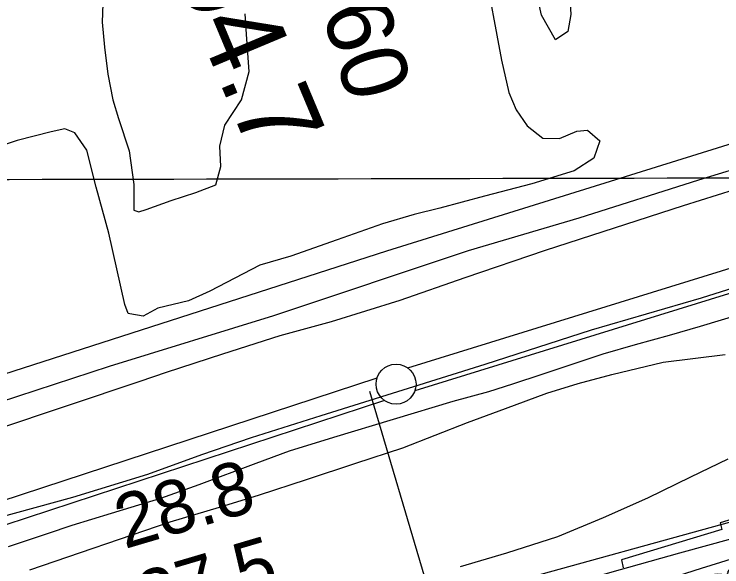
# Model space of a CAD drawing. Extents: x 3324104 to 3361979, y 612876 to 638273.
# Drawn here: x 3357621 to 3358506, y 623884 to 624575 of the extents above; entities that cross this region are included whole.
import ezdxf

# ---------------------------------------------------------------- set-up
doc = ezdxf.new("R2010")
doc.units = 0
for name, color, linetype in [('V-FLOD-BASE', 7, 'Continuous'), ('V-GRID-MAJR', 7, 'Continuous'), ('V-LEVE-TOET', 7, 'Continuous'), ('V-RIVR-EDGE', 7, 'Continuous'), ('V-RIVR-RANG', 7, 'Continuous'), ('V-RIVR-RANG-IDEN', 7, 'Continuous'), ('V-ROAD-CNTR', 7, 'Continuous'), ('V-RRAP-RVMT', 7, 'Continuous'), ('V-SITE-VEGE', 7, 'Continuous'), ('V-SURV-IDEN', 7, 'Continuous'), ('V-SURV-LINE', 7, 'Continuous'), ('V-TOPO-MAJR', 7, 'Continuous'), ('V-TOPO-MINR', 7, 'Continuous'), ('V-TOPO-SHOR', 7, 'Continuous')]:
    doc.layers.add(name, color=color, linetype=linetype)

msp = doc.modelspace()

# ---------------------------------------------------------------- linework, layer by layer
at = {"layer": 'V-FLOD-BASE'}
msp.add_lwpolyline([(3357573.71, 623938.31), (3357694.33, 623971.45), (3357787.75, 624000.32), (3357855.36, 624024.93), (3357917.4, 624046.04), (3358004.54, 624073.49), (3358209.5, 624137.57), (3358342.65, 624180.51), (3358480, 624220.67), (3358576.2, 624250.94), (3358637.54, 624274.14), (3358756.06, 624310.06), (3358978.46, 624376.27), (3359126.95, 624420.65), (3359170.17, 624435.42)], dxfattribs=at)
at = {"layer": 'V-GRID-MAJR'}
msp.add_spline([(3328209.96, 624318.18), (3333474.02, 624325.46), (3338738.09, 624333.49), (3344002.15, 624342.3), (3349266.22, 624351.87), (3354530.28, 624362.21), (3359794.34, 624373.31)], degree=3, dxfattribs=at)
at = {"layer": 'V-LEVE-TOET'}
for points in [[(3359793.54, 624738.78), (3359769.02, 624731.31), (3359688.87, 624701.08), (3359550.81, 624665.1), (3359476.22, 624641.17), (3359417.66, 624623.56), (3359352.12, 624603.84), (3359273.34, 624581.29), (3359195.96, 624556.65), (3359115.09, 624531.31), (3359046.78, 624508.09), (3358864.81, 624455.94), (3358808.34, 624439.04), (3358629.16, 624387.59), (3358542.01, 624362.23), (3358456.96, 624335.48), (3358284.77, 624279.87), (3358184.39, 624245.4), (3358102.84, 624217.26), (3358017.09, 624190.5), (3357952.94, 624172.88), (3357881.14, 624150.34), (3357810.73, 624127.12)], [(3357613.86, 623909.74), (3357662.66, 623925.93), (3357693.33, 623936.48), (3357767.23, 623959.02), (3357804.18, 623970.29), (3357852.28, 623987.17), (3357923.37, 624013.88), (3357965.19, 624029.35), (3358020.27, 624046.25), (3358169.46, 624091.33), (3358214.08, 624103.31), (3358244.06, 624113.17), (3358281.01, 624125.13), (3358356.99, 624150.47), (3358397.43, 624162.44), (3358439.96, 624173.72), (3358479, 624185), (3358527.1, 624199.79)], [(3357810.73, 624127.12), (3357777.97, 624115.86), (3357596.02, 624055.34)]]:
    msp.add_lwpolyline(points, dxfattribs=at)
at = {"layer": 'V-RIVR-EDGE'}
msp.add_spline([(3359795.11, 624016.82), (3359789.29, 624017.27), (3359775.9, 624016.6), (3359757.21, 624013.48), (3359746.28, 624008.22), (3359732.18, 624007.9), (3359730.42, 624010.02), (3359727.96, 624012.14), (3359719.16, 624015.33), (3359708.94, 624015.01), (3359699.42, 624012.92), (3359694.14, 624013.99), (3359689.92, 624019.28), (3359671.6, 624018.62), (3359656.8, 624018.66), (3359645.88, 624019.39), (3359641.64, 624017.99), (3359635.65, 624018.01), (3359628.96, 624018.73), (3359625.43, 624017.68), (3359622.61, 624015.92), (3359617.68, 624018.4), (3359614.16, 624018.06), (3359610.63, 624015.6), (3359604.63, 624013.85), (3359595.48, 624015.64), (3359584.56, 624016.72), (3359572.23, 624017.81), (3359546.5, 624016.47), (3359518.3, 624014.07), (3359492.92, 624010.96), (3359467.89, 624006.09), (3359449.92, 624003.67), (3359441.81, 624003.33), (3359440.04, 624000.17), (3359435.11, 623999.12), (3359430.88, 623999.13), (3359426.3, 624001.26), (3359420.66, 623999.86), (3359418.54, 623997.75), (3359412.9, 623997.77), (3359403.39, 623999.2), (3359387.53, 623996.77), (3359379.42, 623994.33), (3359374.11, 623986.59), (3359371.64, 623982.36), (3359366.35, 623980.26), (3359359.3, 623979.93), (3359344.83, 623973.27), (3359334.96, 623971.53), (3359325.09, 623970.15), (3359313.83, 623976.16), (3359306.45, 623982.17), (3359301.88, 623987.12), (3359291.31, 623986.79), (3359279.32, 623984.35), (3359273.68, 623981.9), (3359266.97, 623977.34), (3359261.33, 623978.06), (3359255.69, 623977.37), (3359251.11, 623976.32), (3359243, 623974.23), (3359228.55, 623974.26), (3359217.27, 623972.53), (3359198.24, 623972.22), (3359192.24, 623965.89), (3359178.12, 623956.77), (3359170.71, 623951.5), (3359167.54, 623952.57), (3359164.72, 623955.04), (3359158.4, 623961.4), (3359155.93, 623961.76), (3359149.57, 623954.37), (3359141.45, 623949.46), (3359136.16, 623947.71), (3359123.48, 623947.04), (3359098.45, 623944.98), (3359077.31, 623942.92), (3359044.54, 623943), (3359031.85, 623941.62), (3359015.99, 623940.96), (3358974.75, 623938.24), (3358969.12, 623938.61), (3358965.25, 623941.79), (3358956.79, 623943.22), (3358951.15, 623942.53), (3358945.87, 623941.13), (3358933.19, 623943.28), (3358922.27, 623946.12), (3358918.04, 623945.08), (3358916.62, 623942.26), (3358911.68, 623940.16), (3358905.69, 623941.23), (3358905.35, 623943.7), (3358894.06, 623939.85), (3358884.54, 623934.94), (3358876.44, 623937.78), (3358872.92, 623938.49), (3358859.52, 623935), (3358851.07, 623937.14), (3358839.08, 623934), (3358822.87, 623932.63), (3358809.83, 623932.66), (3358783.74, 623926.03), (3358762.24, 623923.97), (3358742.85, 623920.49), (3358726.27, 623914.54), (3358716.39, 623909.28), (3358700.89, 623910.38), (3358684.33, 623909.71), (3358675.17, 623912.55), (3358672, 623914.68), (3358662.84, 623915.05), (3358657.91, 623914.71), (3358643.1, 623910.87), (3358638.88, 623912.64), (3358635.7, 623912.65), (3358618.78, 623909.17), (3358613.5, 623911.3), (3358612.8, 623913.77), (3358612.11, 623917.29), (3358598, 623912.75), (3358575.42, 623901.53), (3358539.09, 623886.82), (3358523.57, 623881.57), (3358512.99, 623878.42), (3358512.63, 623875.96), (3358502.41, 623874.93), (3358488.31, 623871.44), (3358468.91, 623862.32), (3358449.49, 623848.63), (3358433.26, 623838.8), (3358414.21, 623829.69), (3358401.17, 623829.01), (3358394.48, 623831.15), (3358393.43, 623834.32), (3358394.15, 623838.9), (3358393.45, 623842.07), (3358391.69, 623843.13), (3358389.22, 623843.14), (3358388.86, 623837.85), (3358385.33, 623837.86), (3358382.86, 623833.29), (3358381.08, 623829.06), (3358377.9, 623826.25), (3358372.98, 623828.03), (3358366.63, 623827.69), (3358362.39, 623823.82), (3358357.45, 623818.9), (3358350.05, 623817.51), (3358338.4, 623811.9), (3358324.64, 623804.89), (3358314.07, 623802.8), (3358302.08, 623798.96), (3358298.89, 623793.68), (3358291.84, 623793.34), (3358284.44, 623793.01), (3358275.98, 623792.32), (3358269.98, 623787.41), (3358261.86, 623780.03), (3358253.39, 623777.23), (3358241.41, 623775.14), (3358222.72, 623770.96), (3358210.73, 623766.41), (3358198.74, 623761.86), (3358192.02, 623752.01), (3358185.66, 623745.33), (3358171.56, 623742.9), (3358161.68, 623736.23), (3358141.92, 623726.41), (3358128.52, 623723.27), (3358116.53, 623720.83), (3358097.5, 623717.01), (3358087.27, 623715.62), (3358076.7, 623714.24), (3358064.36, 623711.8), (3358053.08, 623709.01), (3358034.03, 623701.66), (3358000.51, 623685.53), (3357981.12, 623681.35), (3357961.38, 623677.88), (3357943.41, 623676.16), (3357922.61, 623674.1), (3357909.2, 623666.73), (3357896.5, 623659.01), (3357880.26, 623648.12), (3357868.25, 623637.23), (3357853.41, 623620), (3357846.69, 623608.39), (3357833.26, 623593.27), (3357819.48, 623579.21)], degree=3, dxfattribs=at)
at = {"layer": 'V-RIVR-RANG'}
msp.add_line((3358064.95, 624104.11), (3358366.42, 623087.86), dxfattribs=at)
at = {"layer": 'V-ROAD-CNTR'}
msp.add_lwpolyline([(3359790.96, 624815.17), (3359721.19, 624794.24), (3359118.54, 624598.32), (3358677.74, 624463), (3358086.28, 624278.84), (3357533.38, 624100.8), (3357044.63, 623937.48)], dxfattribs=at)
at = {"layer": 'V-RRAP-RVMT'}
for p, q in [((3358636.67, 623980.46), (3358503.22, 623939.34)), ((3358505.32, 623931.1), (3358380.1, 623893.02)), ((3358503.22, 623939.34), (3358505.32, 623931.1)), ((3358380.1, 623893.02), (3358382.11, 623882.94))]:
    msp.add_line(p, q, dxfattribs=at)
at = {"layer": 'V-SITE-VEGE'}
for p, q in [((3358432.2, 624140.3), (3358509.81, 624149.61)), ((3358367.9, 624124.73), (3358432.2, 624140.3)), ((3358325.97, 624113.43), (3358367.9, 624124.73)), ((3358286.84, 624101.43), (3358325.97, 624113.43)), ((3358235.14, 624082.4), (3358286.84, 624101.43)), ((3358187.63, 624064.78), (3358235.14, 624082.4)), ((3358106.58, 624033.08), (3358187.63, 624064.78)), ((3358047.89, 624014.03), (3358106.58, 624033.08)), ((3357986.4, 623993.57), (3358047.89, 624014.03)), ((3358512.97, 624018.84), (3358466.18, 623996.33)), ((3357927.71, 623974.53), (3357986.4, 623993.57)), ((3358466.18, 623996.33), (3358412.4, 623970.3)), ((3357877.39, 623959), (3357927.71, 623974.53)), ((3358412.4, 623970.3), (3358357.21, 623945.66)), ((3357815.9, 623940.64), (3357877.39, 623959)), ((3357640.52, 623880.7), (3357815.9, 623940.64)), ((3358357.21, 623945.66), (3358299.93, 623921.72)), ((3358299.93, 623921.72), (3358236.34, 623901.26)), ((3358236.34, 623901.26), (3358178.34, 623884.31))]:
    msp.add_line(p, q, dxfattribs=at)
for points in [[(3358207.9, 624636.36), (3358229.87, 624517.8), (3358239.05, 624477.35), (3358248.18, 624455.75), (3358262.19, 624435.56), (3358281.77, 624420.26), (3358302.71, 624419.62), (3358324.31, 624428.75), (3358337.57, 624430.19), (3358352.95, 624416.97), (3358345.34, 624395.32), (3358320.96, 624379.2), (3358267.98, 624363.01), (3358208.72, 624347.49), (3358152.94, 624332.68), (3358120.86, 624324.91), (3358081.12, 624312.94), (3358024.66, 624293.24), (3357966.8, 624272.84), (3357927.76, 624261.57), (3357865.55, 624228.76), (3357838.93, 624216.76), (3357800.39, 624207.54), (3357782.18, 624197.67), (3357765.34, 624200.43), (3357763.23, 624201.12), (3357759, 624212.33), (3357739.11, 624301.34), (3357723.52, 624358.81), (3357711.46, 624405.06), (3357696.68, 624426.76), (3357684.04, 624431.63), (3357667.22, 624428.08), (3357624.46, 624417.44), (3357544.59, 624390.57)], [(3358314.02, 624615.72), (3358316.92, 624574.56), (3358312.8, 624553.62), (3358297.48, 624543.11), (3358279.95, 624573.76), (3358267.22, 624632.33)], [(3357732.13, 624600.13), (3357730.84, 624565.24), (3357733.71, 624533.85), (3357738, 624500.37), (3357744.37, 624468.29), (3357751.41, 624444.58), (3357764.78, 624404.15), (3357770.48, 624362.3), (3357770.57, 624330.21), (3357776.86, 624328.13), (3357785.92, 624330.95), (3357817.29, 624342.2), (3357847.96, 624352.05), (3357873.06, 624361.89), (3357879.27, 624384.94), (3357877.8, 624410.05), (3357884.01, 624436.58), (3357904.85, 624468.04), (3357914.52, 624503.66), (3357911.62, 624544.12), (3357909.43, 624575.51)]]:
    msp.add_lwpolyline(points, dxfattribs=at)
at = {"layer": 'V-SURV-LINE'}
for points in [[(3358112.83, 624132.92), (3358955.11, 624393.53)], [(3358963.99, 624364.88), (3358121.71, 624104.26)], [(3356845.63, 623717.6), (3358074.52, 624120.71)], [(3358083.85, 624092.19), (3356854.96, 623689.08)]]:
    msp.add_lwpolyline(points, dxfattribs=at)
msp.add_circle((3358098.17, 624112.68), 25, dxfattribs=at)
at = {"layer": 'V-TOPO-MAJR'}
msp.add_lwpolyline([(3358744.36, 624003.27), (3358016.29, 623802.27), (3358000.54, 623797.8), (3357984.83, 623793.19), (3357969.19, 623788.36), (3357953.59, 623783.39), (3357938.03, 623778.28), (3357922.48, 623773.14), (3357906.96, 623767.94), (3357891.44, 623762.7), (3357890.6, 623762.42), (3357874.68, 623757.02), (3357858.75, 623751.63), (3357842.82, 623746.26), (3357826.88, 623740.88), (3357120.75, 623503.14)], dxfattribs=at)
at = {"layer": 'V-TOPO-MINR'}
for points in [[(3359794.95, 624093.1), (3359672.5, 624075.75), (3359658.17, 624073.78), (3359643.83, 624071.89), (3359629.48, 624070.11), (3359615.12, 624068.41), (3358824.89, 623979.78), (3358817.76, 623978.39), (3358810.65, 623976.89), (3358803.59, 623975.2), (3358796.55, 623973.38), (3358699.85, 623947.15), (3358644.59, 623931.76), (3358589.47, 623915.9), (3358534.57, 623899.3), (3358479.8, 623882.23), (3357966.85, 623718.57), (3357954.03, 623714.4), (3357941.24, 623710.15), (3357928.51, 623705.76), (3357915.8, 623701.27), (3357248.01, 623461.72)], [(3358770.45, 623988.37), (3358452.36, 623901.29), (3358365, 623876.74), (3358277.87, 623851.4), (3358191.09, 623824.88), (3358104.55, 623797.58), (3357988.66, 623760.16), (3357960.27, 623750.88), (3357931.92, 623741.48), (3357903.63, 623731.89), (3357875.38, 623722.17), (3357747.93, 623677.83), (3357656.01, 623645.79), (3357564.11, 623613.67)]]:
    msp.add_lwpolyline(points, dxfattribs=at)
at = {"layer": 'V-TOPO-SHOR'}
msp.add_lwpolyline([(3355996.42, 623451.85), (3356154.96, 623531.33), (3356400.82, 623643.92), (3356613.16, 623742.43), (3356803.87, 623822.7), (3356903.08, 623857.95), (3357072.88, 623915.78), (3357254.54, 623979.24), (3357418.75, 624030.06), (3357740.18, 624135.17), (3357945.62, 624198.69), (3358188.78, 624279.81), (3358327.15, 624320.76), (3358476.68, 624368.04), (3358599.67, 624405.46), (3358803.71, 624468.28), (3359039.21, 624540.98), (3359236.26, 624603.08), (3359396.28, 624653.19), (3359557, 624703.3), (3359692.55, 624749.14), (3359793.44, 624782.89)], dxfattribs=at)

# ---------------------------------------------------------------- texts
at = {"layer": 'V-RIVR-RANG'}
for s, p in [('28.8', (3357758.88, 623906.35)), ('27.5', (3357787.42, 623810.51))]:
    msp.add_text(s, height=67, rotation=16.43833, dxfattribs=at).set_placement(p)
at = {"layer": 'V-RIVR-RANG-IDEN'}
msp.add_text('U-160', height=83, rotation=286.38133, dxfattribs=at).set_placement((3357954.49, 624751.27))
at = {"layer": 'V-SURV-IDEN'}
msp.add_text('2033+04.7', height=100, rotation=292.74797, dxfattribs=at).set_placement((3357673.24, 624977.54))

doc.saveas('drawing.dxf')
